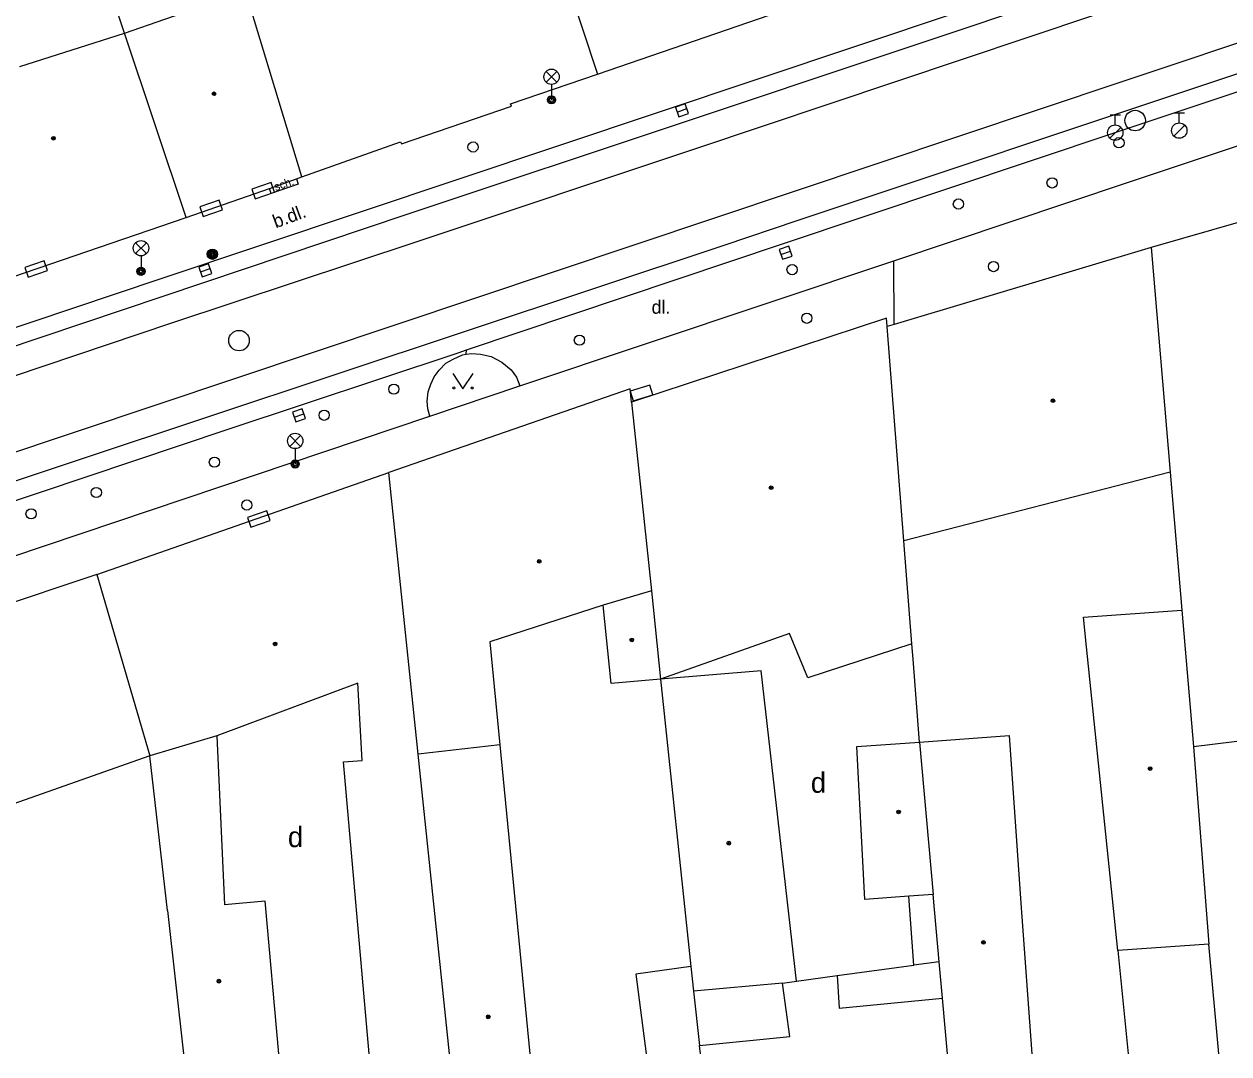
# Model space of a CAD drawing. Extents: x -596229 to -595156, y -1161237 to -1159376.
# Drawn here: x -596026.5 to -595967.8, y -1161235.4 to -1161185.2 of the extents above; entities that cross this region are included whole.
import ezdxf

# ---------------------------------------------------------------- set-up
doc = ezdxf.new("R2010")
doc.units = 0
for name, color, linetype in [('DOP - kresba z DSPS bez souradnic', 7, 'Continuous'), ('DOP - rozhrani ploch obecne', 7, 'Continuous'), ('Level 24', 7, 'Continuous'), ('Level 25', 7, 'Continuous'), ('Level 27', 7, 'Continuous'), ('Level 28', 7, 'Continuous'), ('Level 33', 7, 'Continuous'), ('Level 36', 7, 'Continuous'), ('Level 39', 7, 'Continuous'), ('Level 41', 7, 'Continuous'), ('Specificka linie pasportu komunikaci', 7, 'Continuous'), ('TM - budovy zdene_ betonove - VP', 7, 'Continuous'), ('TM - chodniky - VP', 7, 'Continuous'), ('TM - komunikace - VP', 7, 'Continuous'), ('TM - letecke snimky - pomocna linie', 7, 'Continuous'), ('TM - MHD - osa koleji', 7, 'Continuous'), ('TM - popis povrchu', 7, 'Continuous'), ('TM - poznamka', 7, 'Continuous'), ('TM - rozhrani ploch obecne - VP', 7, 'Continuous'), ('TM - schody - NP', 7, 'Continuous')]:
    doc.layers.add(name, color=color, linetype=linetype)

msp = doc.modelspace()

# ---------------------------------------------------------------- linework, layer by layer
at = {"layer": 'DOP - kresba z DSPS bez souradnic'}
for points in [[(-595983.13, -1161231.09), (-595983.37, -1161227.73)], [(-595994, -1161231.16), (-595996.69, -1161231.53)], [(-595986.87, -1161231.6), (-595983.13, -1161231.09)], [(-595981.9, -1161230.92), (-595983.13, -1161231.09)], [(-595996.69, -1161231.53), (-595996.188, -1161235.417)]]:
    msp.add_lwpolyline(points, dxfattribs=at)
at = {"layer": 'DOP - rozhrani ploch obecne'}
for points in [[(-595983.17, -1161216.17), (-595983.23, -1161215.42)], [(-595982.86, -1161220.21), (-595983.17, -1161216.17)], [(-595988.85, -1161231.87), (-595986.87, -1161231.6)], [(-595986.87, -1161231.6), (-595986.77, -1161233.18)], [(-595986.77, -1161233.18), (-595981.73, -1161232.7)], [(-595993.541, -1161235.417), (-595993.59, -1161235.01)]]:
    msp.add_lwpolyline(points, dxfattribs=at)
at = {"layer": 'Level 24'}
for points in [[(-596015.249, -1161193.724), (-596014.304, -1161193.396), (-596014.468, -1161192.924), (-596015.413, -1161193.252)], [(-596017.789, -1161194.576), (-596016.845, -1161194.247), (-596017.009, -1161193.775), (-596017.953, -1161194.103)], [(-596026.321, -1161197.532), (-596025.374, -1161197.209), (-596025.536, -1161196.736), (-596026.482, -1161197.059)], [(-595996.815, -1161203.576), (-595995.859, -1161203.282), (-595996.005, -1161202.804), (-595996.961, -1161203.098)], [(-596014.681, -1161208.926), (-596015.626, -1161209.253), (-596015.462, -1161209.726), (-596014.517, -1161209.399)]]:
    msp.add_lwpolyline(points, close=True, dxfattribs=at)
at = {"layer": 'Level 25'}
for radius in [0.25, 0.2, 0.15, 0.1, 0.05]:
    msp.add_circle((-596017.34, -1161196.42), radius, dxfattribs=at)
at = {"layer": 'Level 27'}
for p, q in [((-595994.676, -1161189.484), (-595994.204, -1161189.316)), ((-595989.617, -1161196.431), (-595989.143, -1161196.269)), ((-596017.916, -1161197.282), (-596017.444, -1161197.118)), ((-596013.346, -1161204.364), (-596012.874, -1161204.196))]:
    msp.add_line(p, q, dxfattribs=at)
for points in [[(-595994.592, -1161189.719), (-595994.121, -1161189.552), (-595994.288, -1161189.081), (-595994.759, -1161189.248)], [(-595989.536, -1161196.667), (-595989.063, -1161196.506), (-595989.224, -1161196.033), (-595989.697, -1161196.194)], [(-596017.834, -1161197.518), (-596017.362, -1161197.354), (-596017.526, -1161196.882), (-596017.998, -1161197.046)], [(-596013.262, -1161204.599), (-596012.791, -1161204.432), (-596012.958, -1161203.961), (-596013.429, -1161204.128)]]:
    msp.add_lwpolyline(points, close=True, dxfattribs=at)
for centre in [(-595972.34, -1161189.9), (-596016.04, -1161200.63)]:
    msp.add_circle(centre, 0.5, dxfattribs=at)
at = {"layer": 'Level 28'}
for p, q in [((-595970.44, -1161189.515), (-595969.94, -1161189.515)), ((-595970.19, -1161190.015), (-595970.19, -1161189.515)), ((-595973.56, -1161189.615), (-595973.06, -1161189.615)), ((-595973.31, -1161190.115), (-595973.31, -1161189.615)), ((-595973.568, -1161190.762), (-595973.038, -1161190.232)), ((-595970.448, -1161190.662), (-595969.918, -1161190.132))]:
    msp.add_line(p, q, dxfattribs=at)
for centre, radius in [((-595973.31, -1161190.49), 0.375), ((-595970.19, -1161190.39), 0.375), ((-596004.63, -1161191.19), 0.25), ((-595973.13, -1161190.98), 0.25), ((-595976.39, -1161192.94), 0.25), ((-595980.96, -1161193.97), 0.25), ((-595989.07, -1161197.17), 0.25), ((-595979.25, -1161197.02), 0.25), ((-595988.35, -1161199.54), 0.25), ((-595999.44, -1161200.61), 0.25), ((-596008.49, -1161203), 0.25), ((-596011.89, -1161204.27), 0.25), ((-596017.24, -1161206.56), 0.25), ((-596023, -1161208.04), 0.25), ((-596026.18, -1161209.08), 0.25), ((-596015.66, -1161208.65), 0.25)]:
    msp.add_circle(centre, radius, dxfattribs=at)
at = {"layer": 'Level 33'}
for p, q in [((-596001.065, -1161188.03), (-596000.535, -1161187.5)), ((-596001.065, -1161187.5), (-596000.535, -1161188.03)), ((-596000.8, -1161188.14), (-596000.8, -1161188.89)), ((-596021.085, -1161196.39), (-596020.555, -1161195.86)), ((-596021.085, -1161195.86), (-596020.555, -1161196.39)), ((-596020.82, -1161196.5), (-596020.82, -1161197.25)), ((-596013.565, -1161205.79), (-596013.035, -1161205.26)), ((-596013.565, -1161205.26), (-596013.035, -1161205.79)), ((-596013.3, -1161205.9), (-596013.3, -1161206.65))]:
    msp.add_line(p, q, dxfattribs=at)
for centre, radius in [((-596000.8, -1161187.765), 0.375), ((-596000.8, -1161188.89), 0.2), ((-596000.8, -1161188.89), 0.145), ((-596000.8, -1161188.89), 0.0876), ((-596020.82, -1161196.125), 0.375), ((-596020.82, -1161197.25), 0.2), ((-596020.82, -1161197.25), 0.145), ((-596020.82, -1161197.25), 0.0876), ((-596013.3, -1161205.525), 0.375), ((-596013.3, -1161206.65), 0.2), ((-596013.3, -1161206.65), 0.145), ((-596013.3, -1161206.65), 0.0876)]:
    msp.add_circle(centre, radius, dxfattribs=at)
at = {"layer": 'Level 36'}
msp.add_lwpolyline([(-596005.62, -1161202.24), (-596005.12, -1161202.99), (-596004.62, -1161202.24)], dxfattribs=at)
for centre in [(-596005.57, -1161202.94), (-596004.671, -1161202.94)]:
    msp.add_circle(centre, 0.05, dxfattribs=at)
at = {"layer": 'Level 39'}
for centre, radius in [((-596017.26, -1161188.59), 0.09), ((-596017.26, -1161188.59), 0.0398), ((-596025.09, -1161190.76), 0.09), ((-596025.09, -1161190.76), 0.0398), ((-595976.35, -1161203.56), 0.09), ((-595976.35, -1161203.56), 0.0398), ((-595990.09, -1161207.81), 0.09), ((-595990.09, -1161207.81), 0.0398), ((-596001.4, -1161211.4), 0.09), ((-596001.4, -1161211.4), 0.0398), ((-596014.28, -1161215.42), 0.09), ((-596014.28, -1161215.42), 0.0398), ((-595996.89, -1161215.23), 0.09), ((-595996.89, -1161215.23), 0.0398), ((-595971.61, -1161221.5), 0.09), ((-595971.61, -1161221.5), 0.0398), ((-595983.88, -1161223.62), 0.09), ((-595983.88, -1161223.62), 0.0398), ((-595992.16, -1161225.14), 0.09), ((-595992.16, -1161225.14), 0.0398), ((-595979.74, -1161229.98), 0.09), ((-595979.74, -1161229.98), 0.0398), ((-596017.02, -1161231.87), 0.09), ((-596017.02, -1161231.87), 0.0398), ((-596003.89, -1161233.61), 0.09), ((-596003.89, -1161233.61), 0.0398)]:
    msp.add_circle(centre, radius, dxfattribs=at)
at = {"layer": 'Specificka linie pasportu komunikaci'}
for points in [[(-595984.1, -1161199.85), (-595984.11, -1161196.74)], [(-596004.96, -1161201.3), (-596004.95, -1161201.08)]]:
    msp.add_lwpolyline(points, dxfattribs=at)
at = {"layer": 'TM - budovy zdene_ betonove - VP'}
for points in [[(-596001.58, -1161178.49), (-595998.56, -1161187.63)], [(-596021.63, -1161185.63), (-596022.92, -1161181.72)], [(-596021.63, -1161185.63), (-596015.73, -1161183.57)], [(-596012.97, -1161192.65), (-596015.73, -1161183.57)], [(-595998.56, -1161187.63), (-595986.5, -1161183.48)], [(-596026.73, -1161187.27), (-596021.63, -1161185.63)], [(-596018.62, -1161194.63), (-596021.63, -1161185.63)], [(-596002.8, -1161189.09), (-595998.56, -1161187.63)], [(-596008.12, -1161191.04), (-596002.76, -1161189.19)], [(-596002.76, -1161189.19), (-596002.8, -1161189.09)], [(-596012.97, -1161192.65), (-596008.16, -1161190.93)], [(-596008.16, -1161190.93), (-596008.12, -1161191.04)], [(-596014.56, -1161193.22), (-596013.24, -1161192.74)], [(-596013.24, -1161192.74), (-596012.97, -1161192.65)], [(-596018.62, -1161194.63), (-596014.56, -1161193.22)], [(-595964.15, -1161193.96), (-595971.56, -1161196.09)], [(-596027.71, -1161197.73), (-596018.62, -1161194.63)], [(-595971.56, -1161196.09), (-595984.1, -1161199.85)], [(-595971.56, -1161196.09), (-595970.63, -1161207.05)], [(-595984.46, -1161199.54), (-595996.9, -1161203.64)], [(-595984.43, -1161199.95), (-595984.46, -1161199.54)], [(-595984.1, -1161199.85), (-595984.43, -1161199.95)], [(-595983.62, -1161210.4), (-595984.43, -1161199.95)], [(-595996.97, -1161202.98), (-596008.73, -1161207.07)], [(-595996.9, -1161203.64), (-595996.97, -1161202.98)], [(-595996.9, -1161203.64), (-595995.93, -1161212.84)], [(-596022.97, -1161212.03), (-596008.73, -1161207.07)], [(-596007.3, -1161220.8), (-596008.73, -1161207.07)], [(-595970.63, -1161207.05), (-595983.62, -1161210.4)], [(-595970.63, -1161207.05), (-595970.06, -1161213.77)], [(-595983.23, -1161215.42), (-595983.62, -1161210.4)], [(-596022.97, -1161212.03), (-596028.15, -1161213.76)], [(-596022.97, -1161212.03), (-596020.39, -1161220.88)], [(-595995.93, -1161212.84), (-595998.29, -1161213.53)], [(-595995.93, -1161212.84), (-595995.48, -1161217.14)], [(-595998.29, -1161213.53), (-596003.81, -1161215.32)], [(-595997.89, -1161217.35), (-595998.29, -1161213.53)], [(-595974.86, -1161214.12), (-595970.06, -1161213.77)], [(-595974.71, -1161215.56), (-595974.86, -1161214.12)], [(-595970.06, -1161213.77), (-595969.5, -1161220.43)], [(-596003.81, -1161215.32), (-596003.32, -1161220.34)], [(-595989.19, -1161214.91), (-595995.48, -1161217.14)], [(-595988.3, -1161217.08), (-595989.19, -1161214.91)], [(-595983.23, -1161215.42), (-595988.3, -1161217.08)], [(-595973.19, -1161230.38), (-595974.71, -1161215.56)], [(-595995.48, -1161217.14), (-595997.89, -1161217.35)], [(-595990.58, -1161216.73), (-595995.48, -1161217.14)], [(-595995.48, -1161217.14), (-595994, -1161231.16)], [(-595988.85, -1161231.87), (-595990.58, -1161216.73)], [(-596010.25, -1161217.33), (-596017.13, -1161219.91)], [(-596010.03, -1161221.11), (-596010.25, -1161217.33)], [(-596017.13, -1161219.91), (-596020.39, -1161220.88)], [(-596017.13, -1161219.91), (-596016.75, -1161228.15)], [(-595982.86, -1161220.21), (-595978.49, -1161219.89)], [(-595978.49, -1161219.89), (-595977.91, -1161228.06)], [(-595969.5, -1161220.43), (-595965.53, -1161219.94)], [(-596003.32, -1161220.34), (-596007.3, -1161220.8)], [(-596003.32, -1161220.34), (-596001.854, -1161235.417)], [(-595985.92, -1161220.43), (-595982.86, -1161220.21)], [(-595985.53, -1161227.88), (-595985.92, -1161220.43)], [(-595982.86, -1161220.21), (-595982.19, -1161227.65)], [(-595969.5, -1161220.43), (-595968.75, -1161230.06)], [(-596020.39, -1161220.88), (-596030.68, -1161224.5)], [(-596019.53, -1161228.42), (-596020.39, -1161220.88)], [(-596010.95, -1161221.17), (-596010.03, -1161221.11)], [(-596009.692, -1161235.417), (-596010.95, -1161221.17)], [(-596005.78, -1161235.417), (-596007.3, -1161220.8)], [(-595982.19, -1161227.65), (-595983.37, -1161227.73)], [(-595981.9, -1161230.92), (-595982.19, -1161227.65)], [(-596014.76, -1161227.97), (-596016.75, -1161228.15)], [(-596014.098, -1161235.417), (-596014.76, -1161227.97)], [(-595983.37, -1161227.73), (-595985.53, -1161227.88)], [(-595977.91, -1161228.06), (-595977.385, -1161235.417)], [(-596019.53, -1161228.42), (-596018.749, -1161235.417)], [(-595968.75, -1161230.06), (-595973.19, -1161230.38)], [(-595968.267, -1161235.417), (-595968.75, -1161230.06)], [(-595973.19, -1161230.38), (-595972.678, -1161235.417)], [(-595994, -1161231.16), (-595993.87, -1161232.36)], [(-595981.73, -1161232.7), (-595981.9, -1161230.92)], [(-595993.87, -1161232.36), (-595993.59, -1161235.01)], [(-595989.54, -1161231.97), (-595988.85, -1161231.87)], [(-595989.18, -1161234.57), (-595989.54, -1161231.97)], [(-595981.486, -1161235.417), (-595981.73, -1161232.7)], [(-595993.59, -1161235.01), (-595989.18, -1161234.57)]]:
    msp.add_lwpolyline(points, dxfattribs=at)
at = {"layer": 'TM - chodniky - VP'}
msp.add_lwpolyline([(-596006.74, -1161204.31), (-596002.34, -1161202.84)], dxfattribs=at)
at = {"layer": 'TM - komunikace - VP'}
for points in [[(-596041.07, -1161204.75), (-596034.62, -1161202.56), (-596019.88, -1161197.62), (-595981.06, -1161184.63)], [(-595984.11, -1161196.74), (-595972.71, -1161192.92), (-595955.81, -1161187.28)], [(-596002.34, -1161202.84), (-595984.11, -1161196.74)], [(-596004.96, -1161201.3), (-596004.69, -1161201.26), (-596004.26, -1161201.3), (-596003.75, -1161201.4), (-596003.22, -1161201.68), (-596002.77, -1161202.06), (-596002.51, -1161202.42), (-596002.34, -1161202.84)], [(-596006.74, -1161204.31), (-596006.83, -1161203.96), (-596006.86, -1161203.58), (-596006.81, -1161203.13), (-596006.69, -1161202.75), (-596006.53, -1161202.4), (-596006.28, -1161202.08), (-596005.96, -1161201.73), (-596005.6, -1161201.54), (-596005.14, -1161201.33), (-596004.96, -1161201.3)], [(-596033.99, -1161213.49), (-596006.74, -1161204.31)]]:
    msp.add_lwpolyline(points, dxfattribs=at)
at = {"layer": 'TM - letecke snimky - pomocna linie'}
for points in [[(-596114.37, -1161230.84), (-596110.09, -1161230.02), (-596106.3, -1161229.01), (-596101.55, -1161227.51), (-596075.04, -1161217.54), (-596057.03, -1161211.03), (-596047.06, -1161207.64), (-596033.59, -1161203.11), (-596007.84, -1161194.47), (-595994.17, -1161189.91), (-595974.75, -1161183.41), (-595950.17, -1161175.18), (-595940.94, -1161172.12)], [(-595939.83, -1161178.35), (-595948.35, -1161181.26), (-595988.84, -1161194.79), (-595992.4, -1161196), (-596036.52, -1161210.65), (-596036.29, -1161210.57), (-596041.11, -1161212.17), (-596057.19, -1161217.84), (-596072.83, -1161223.49), (-596089.07, -1161229.53), (-596093.1, -1161231.04), (-596093.41, -1161231.16), (-596097.49, -1161232.69), (-596100.53, -1161233.83)]]:
    msp.add_lwpolyline(points, dxfattribs=at)
at = {"layer": 'TM - MHD - osa koleji'}
for points in [[(-595948.8, -1161179.92), (-595973.04, -1161188.03)], [(-596028.64, -1161202.9), (-596019.32, -1161199.77), (-596007.4, -1161195.81), (-595993.72, -1161191.25), (-595974.3, -1161184.74)], [(-595973.04, -1161188.03), (-595992.85, -1161194.66)], [(-595992.85, -1161194.66), (-596027.93, -1161206.39)]]:
    msp.add_lwpolyline(points, dxfattribs=at)
at = {"layer": 'TM - rozhrani ploch obecne - VP'}
for points in [[(-596004.95, -1161201.08), (-595989.53, -1161195.91), (-595973.32, -1161190.48), (-595958.8, -1161185.64)], [(-596013.24, -1161192.74), (-596013.15, -1161193), (-596014.48, -1161193.46), (-596014.56, -1161193.22)], [(-596065.58, -1161221.73), (-596052.29, -1161216.98), (-596037.11, -1161211.85), (-596016.62, -1161204.97), (-596005.36, -1161201.22), (-596004.95, -1161201.08)], [(-595989.54, -1161231.97), (-595993.87, -1161232.36)]]:
    msp.add_lwpolyline(points, dxfattribs=at)
at = {"layer": 'TM - schody - NP'}
msp.add_lwpolyline([(-596013.24, -1161192.74), (-596013.15, -1161193), (-596014.48, -1161193.46), (-596014.56, -1161193.22)], dxfattribs=at)

# ---------------------------------------------------------------- texts
at = {"layer": 'Level 41'}
for p in [(-595988.157, -1161222.685), (-596013.657, -1161225.335)]:
    msp.add_text('d', height=1, dxfattribs=at).set_placement(p)
at = {"layer": 'TM - popis povrchu'}
msp.add_text('b.dl.', height=0.65, rotation=20.26294, dxfattribs=at).set_placement((-596014.25, -1161195.16))
msp.add_text('dl.', height=0.65, dxfattribs=at).set_placement((-595995.92, -1161199.32))
at = {"layer": 'TM - poznamka'}
msp.add_text('sch.', height=0.4, rotation=19.07869, dxfattribs=at).set_placement((-596014.25, -1161193.34))

doc.saveas('drawing.dxf')
